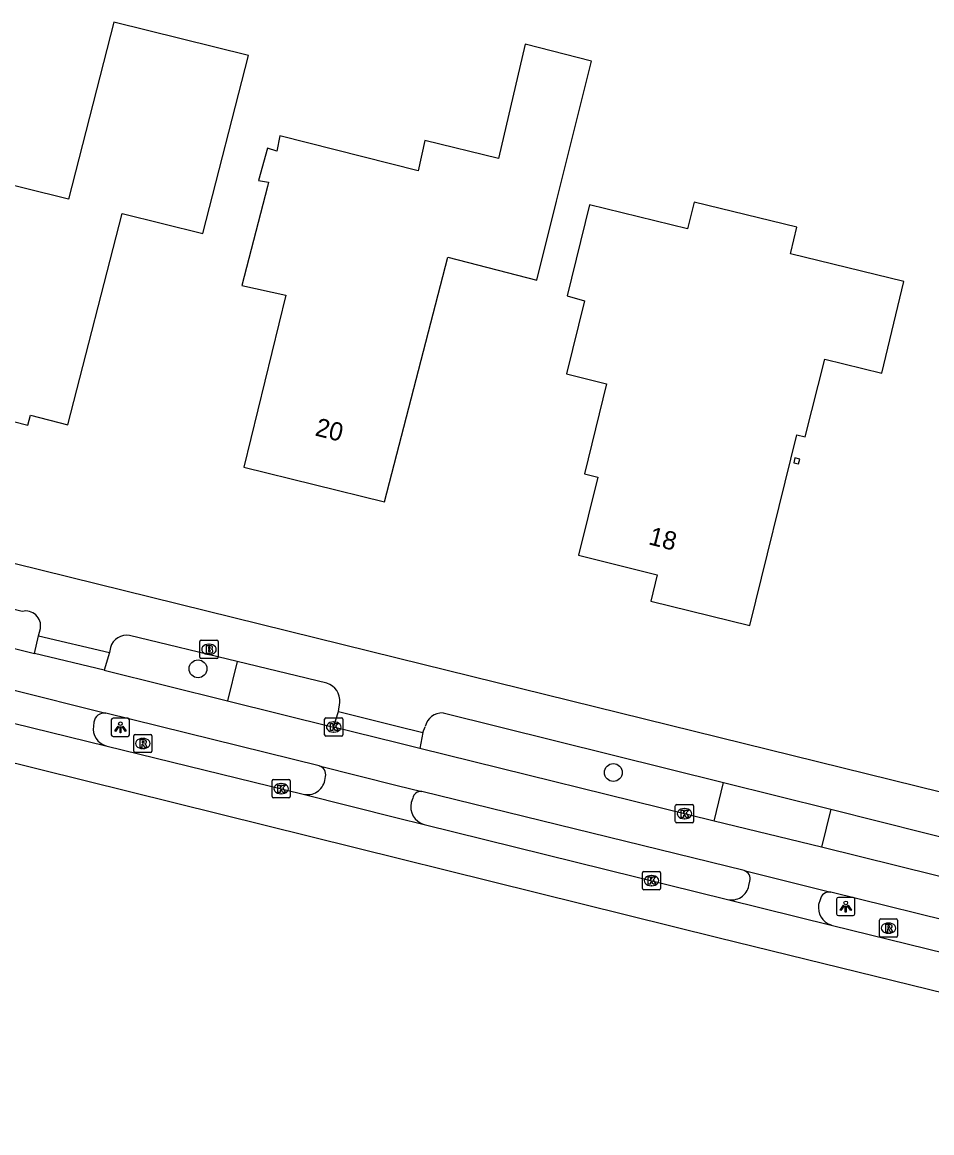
# Model space of a CAD drawing. Extents: x 161354 to 161876, y 382161 to 382804.
# Drawn here: x 161479.4 to 161529.3, y 382164.9 to 382225.8 of the extents above; entities that cross this region are included whole.
import ezdxf

# ---------------------------------------------------------------- set-up
doc = ezdxf.new("R2010")
doc.units = 0
for name, color, linetype in [('IMGEO_Berm_groen', 7, 'Continuous'), ('IMGEO_Boom', 7, 'Continuous'), ('IMGEO_Brandkraan', 7, 'Continuous'), ('IMGEO_Fietspad_gesloten', 7, 'Continuous'), ('IMGEO_Kolk', 7, 'Continuous'), ('IMGEO_Lichtpunt', 7, 'Continuous'), ('IMGEO_Pand', 7, 'Continuous'), ('IMGEO_Pand_nummerreeks', 7, 'Continuous'), ('IMGEO_Parkeervlak_gesloten', 7, 'Continuous'), ('IMGEO_Rijbaan_lokaal_gesloten', 7, 'Continuous'), ('IMGEO_Rioolput', 7, 'Continuous'), ('IMGEO_Voetpad_open', 7, 'Continuous')]:
    doc.layers.add(name, color=color, linetype=linetype)

msp = doc.modelspace()

# ---------------------------------------------------------------- linework, layer by layer
at = {"layer": 'IMGEO_Berm_groen'}
msp.add_lwpolyline([(161491.219, 382190.757), (161490.686, 382188.602)], dxfattribs=at)
at = {"layer": 'IMGEO_Boom'}
for centre in [(161489.073, 382190.355), (161511.843, 382184.67)]:
    msp.add_circle(centre, 0.489, dxfattribs=at)
at = {"layer": 'IMGEO_Brandkraan'}
for p, q in [((161489.175, 382190.993), (161489.175, 382191.845)), ((161489.25, 382191.919), (161490.102, 382191.919)), ((161489.663, 382191.699), (161489.688, 382191.699)), ((161490.176, 382191.845), (161490.176, 382190.993)), ((161490.102, 382190.919), (161489.25, 382190.919)), ((161489.686, 382191.139), (161489.661, 382191.139))]:
    msp.add_line(p, q, dxfattribs=at)
for points in [[(161489.175, 382190.993), (161489.175, 382191.845)], [(161489.25, 382191.919), (161490.102, 382191.919)], [(161489.523, 382191.619), (161489.523, 382191.219), (161489.736, 382191.219)], [(161489.754, 382191.619), (161489.523, 382191.619)], [(161489.702, 382191.538), (161489.648, 382191.538), (161489.648, 382191.462)], [(161490.176, 382191.845), (161490.176, 382190.993)], [(161490.102, 382190.919), (161489.25, 382190.919)], [(161489.648, 382191.462), (161489.701, 382191.462)], [(161489.71, 382191.386), (161489.648, 382191.386), (161489.648, 382191.305)], [(161489.648, 382191.305), (161489.71, 382191.305)]]:
    msp.add_lwpolyline(points, dxfattribs=at)
for centre, radius, start, end in [((161489.252, 382191.843), 0.0765, 91.55205, 178.44795), ((161489.252, 382191.843), 0.0765, 91.55205, 178.44795), ((161489.703, 382191.5), 0.0379, 267.82845, 90.93552), ((161489.758, 382191.474), 0.145, 59.4692, 91.53667), ((161489.783, 382191.521), 0.0922, 285.51372, 58.15012), ((161490.1, 382191.843), 0.0765, 1.55205, 88.44795), ((161490.1, 382191.843), 0.0765, 1.55205, 88.44795), ((161489.252, 382190.995), 0.0765, 181.55205, 268.44795), ((161489.252, 382190.995), 0.0765, 181.55205, 268.44795), ((161489.711, 382191.345), 0.0404, 269.87594, 90.50774), ((161489.742, 382191.47), 0.251, 268.66757, 293.53466), ((161489.788, 382191.329), 0.105, 301.31148, 78.98903), ((161490.1, 382190.995), 0.0765, 271.55205, 358.44795), ((161490.1, 382190.995), 0.0765, 271.55205, 358.44795)]:
    msp.add_arc(centre, radius, start, end, dxfattribs=at)
for centre, major_axis, ratio, start_param, end_param in [((161489.662, 382191.419), (-0.387, 0.002), 0.722429, 4.712389, 7.853982), ((161489.687, 382191.419), (-0.39, 0.002), 0.717154, 1.570796, 4.712389)]:
    msp.add_ellipse(centre, major_axis=major_axis, ratio=ratio, start_param=start_param, end_param=end_param, dxfattribs=at)
at = {"layer": 'IMGEO_Fietspad_gesloten'}
for points in [[(161466.523, 382194.566), (161480.111, 382191.197)], [(161483.93, 382190.272), (161480.111, 382191.197)], [(161483.93, 382190.272), (161490.686, 382188.602)], [(161478.779, 382189.246), (161484.015, 382187.92)], [(161490.686, 382188.602), (161496.51, 382187.162)], [(161495.709, 382185.028), (161484.015, 382187.92)], [(161501.233, 382185.995), (161500, 382186.3), (161496.51, 382187.162)], [(161517.367, 382182.012), (161501.233, 382185.995)], [(161495.709, 382185.028), (161500, 382183.961), (161501.342, 382183.627)], [(161519.01, 382179.306), (161501.342, 382183.627)], [(161523.26, 382180.579), (161517.367, 382182.012)], [(161539.929, 382176.444), (161523.26, 382180.579)], [(161519.01, 382179.306), (161523.769, 382178.11)], [(161539.444, 382174.246), (161523.769, 382178.11)]]:
    msp.add_lwpolyline(points, dxfattribs=at)
at = {"layer": 'IMGEO_Kolk'}
for p, q in [((161496.014, 382186.738), (161496.014, 382187.59)), ((161496.089, 382187.664), (161496.941, 382187.664)), ((161496.502, 382187.444), (161496.527, 382187.444)), ((161497.015, 382187.59), (161497.015, 382186.738)), ((161496.941, 382186.664), (161496.089, 382186.664)), ((161496.525, 382186.884), (161496.5, 382186.884)), ((161493.133, 382183.357), (161493.133, 382184.209)), ((161493.208, 382184.283), (161494.06, 382184.283)), ((161494.134, 382184.209), (161494.134, 382183.357)), ((161493.621, 382184.063), (161493.646, 382184.063)), ((161494.06, 382183.283), (161493.208, 382183.283)), ((161493.644, 382183.503), (161493.619, 382183.503)), ((161515.242, 382181.987), (161515.242, 382182.839)), ((161515.317, 382182.913), (161516.169, 382182.913)), ((161515.73, 382182.693), (161515.755, 382182.693)), ((161516.243, 382182.839), (161516.243, 382181.987)), ((161516.169, 382181.913), (161515.317, 382181.913)), ((161515.753, 382182.133), (161515.728, 382182.133)), ((161513.435, 382178.322), (161513.435, 382179.174)), ((161513.51, 382179.248), (161514.362, 382179.248)), ((161513.923, 382179.028), (161513.948, 382179.028)), ((161514.436, 382179.174), (161514.436, 382178.322)), ((161514.362, 382178.248), (161513.51, 382178.248)), ((161513.946, 382178.468), (161513.921, 382178.468))]:
    msp.add_line(p, q, dxfattribs=at)
for points in [[(161496.014, 382186.738), (161496.014, 382187.59)], [(161496.089, 382187.664), (161496.941, 382187.664)], [(161496.335, 382187.364), (161496.458, 382187.364), (161496.458, 382187.213), (161496.588, 382187.364), (161496.752, 382187.364), (161496.606, 382187.213), (161496.759, 382186.964), (161496.607, 382186.964), (161496.522, 382187.128), (161496.458, 382187.061), (161496.458, 382186.964), (161496.335, 382186.964), (161496.335, 382187.364)], [(161497.015, 382187.59), (161497.015, 382186.738)], [(161496.941, 382186.664), (161496.089, 382186.664)], [(161493.133, 382183.357), (161493.133, 382184.209)], [(161493.208, 382184.283), (161494.06, 382184.283)], [(161494.134, 382184.209), (161494.134, 382183.357)], [(161493.454, 382183.983), (161493.577, 382183.983), (161493.577, 382183.832), (161493.707, 382183.983), (161493.871, 382183.983), (161493.725, 382183.832), (161493.878, 382183.583), (161493.726, 382183.583), (161493.641, 382183.747), (161493.577, 382183.68), (161493.577, 382183.583), (161493.454, 382183.583), (161493.454, 382183.983)], [(161494.06, 382183.283), (161493.208, 382183.283)], [(161515.242, 382181.987), (161515.242, 382182.839)], [(161515.317, 382182.913), (161516.169, 382182.913)], [(161515.563, 382182.613), (161515.686, 382182.613), (161515.686, 382182.462), (161515.816, 382182.613), (161515.98, 382182.613), (161515.834, 382182.462), (161515.987, 382182.213), (161515.835, 382182.213), (161515.75, 382182.377), (161515.686, 382182.31), (161515.686, 382182.213), (161515.563, 382182.213), (161515.563, 382182.613)], [(161516.243, 382182.839), (161516.243, 382181.987)], [(161516.169, 382181.913), (161515.317, 382181.913)], [(161513.435, 382178.322), (161513.435, 382179.174)], [(161513.51, 382179.248), (161514.362, 382179.248)], [(161513.756, 382178.948), (161513.879, 382178.948), (161513.879, 382178.797), (161514.009, 382178.948), (161514.173, 382178.948), (161514.027, 382178.797), (161514.18, 382178.548), (161514.028, 382178.548), (161513.943, 382178.712), (161513.879, 382178.645), (161513.879, 382178.548), (161513.756, 382178.548), (161513.756, 382178.948)], [(161514.436, 382179.174), (161514.436, 382178.322)], [(161514.362, 382178.248), (161513.51, 382178.248)]]:
    msp.add_lwpolyline(points, dxfattribs=at)
for centre, start, end in [((161496.091, 382187.588), 91.55205, 178.44795), ((161496.091, 382187.588), 91.55205, 178.44795), ((161496.939, 382187.588), 1.55205, 88.44795), ((161496.939, 382187.588), 1.55205, 88.44795), ((161496.091, 382186.74), 181.55205, 268.44795), ((161496.091, 382186.74), 181.55205, 268.44795), ((161496.939, 382186.74), 271.55205, 358.44795), ((161496.939, 382186.74), 271.55205, 358.44795), ((161493.21, 382184.207), 91.55205, 178.44795), ((161493.21, 382184.207), 91.55205, 178.44795), ((161494.058, 382184.207), 1.55205, 88.44795), ((161494.058, 382184.207), 1.55205, 88.44795), ((161493.21, 382183.359), 181.55205, 268.44795), ((161493.21, 382183.359), 181.55205, 268.44795), ((161494.058, 382183.359), 271.55205, 358.44795), ((161494.058, 382183.359), 271.55205, 358.44795), ((161515.319, 382182.837), 91.55205, 178.44795), ((161515.319, 382182.837), 91.55205, 178.44795), ((161516.167, 382182.837), 1.55205, 88.44795), ((161516.167, 382182.837), 1.55205, 88.44795), ((161515.319, 382181.989), 181.55205, 268.44795), ((161515.319, 382181.989), 181.55205, 268.44795), ((161516.167, 382181.989), 271.55205, 358.44795), ((161516.167, 382181.989), 271.55205, 358.44795), ((161513.512, 382179.172), 91.55205, 178.44795), ((161513.512, 382179.172), 91.55205, 178.44795), ((161514.36, 382179.172), 1.55205, 88.44795), ((161514.36, 382179.172), 1.55205, 88.44795), ((161513.512, 382178.324), 181.55205, 268.44795), ((161513.512, 382178.324), 181.55205, 268.44795), ((161514.36, 382178.324), 271.55205, 358.44795), ((161514.36, 382178.324), 271.55205, 358.44795)]:
    msp.add_arc(centre, 0.0765, start, end, dxfattribs=at)
for centre, major_axis, ratio, start_param, end_param in [((161496.501, 382187.164), (-0.387, 0.002), 0.722429, 4.712389, 7.853982), ((161496.526, 382187.164), (-0.39, 0.002), 0.717154, 1.570796, 4.712389), ((161493.62, 382183.783), (-0.387, 0.002), 0.722429, 4.712389, 7.853982), ((161493.645, 382183.783), (-0.39, 0.002), 0.717154, 1.570796, 4.712389), ((161515.729, 382182.413), (-0.387, 0.002), 0.722429, 4.712389, 7.853982), ((161515.754, 382182.413), (-0.39, 0.002), 0.717154, 1.570796, 4.712389), ((161513.922, 382178.748), (-0.387, 0.002), 0.722429, 4.712389, 7.853982), ((161513.947, 382178.748), (-0.39, 0.002), 0.717154, 1.570796, 4.712389)]:
    msp.add_ellipse(centre, major_axis=major_axis, ratio=ratio, start_param=start_param, end_param=end_param, dxfattribs=at)
at = {"layer": 'IMGEO_Lichtpunt'}
for p, q in [((161484.321, 382187.549), (161484.321, 382186.742)), ((161484.321, 382187.549), (161484.321, 382186.742)), ((161485.223, 382187.644), (161484.415, 382187.644)), ((161485.223, 382187.644), (161484.415, 382187.644)), ((161485.317, 382186.742), (161485.317, 382187.549)), ((161485.317, 382186.742), (161485.317, 382187.549)), ((161484.415, 382186.648), (161485.223, 382186.648)), ((161484.415, 382186.648), (161485.223, 382186.648)), ((161524.085, 382177.73), (161524.085, 382176.923)), ((161524.085, 382177.73), (161524.085, 382176.923)), ((161524.987, 382177.825), (161524.179, 382177.825)), ((161524.987, 382177.825), (161524.179, 382177.825)), ((161525.081, 382176.923), (161525.081, 382177.73)), ((161525.081, 382176.923), (161525.081, 382177.73)), ((161524.179, 382176.829), (161524.987, 382176.829)), ((161524.179, 382176.829), (161524.987, 382176.829))]:
    msp.add_line(p, q, dxfattribs=at)
for points in [[(161484.695, 382187.213), (161484.734, 382187.185), (161484.546, 382186.923), (161484.508, 382186.95), (161484.695, 382187.213)], [(161484.797, 382187.165), (161484.844, 382187.165), (161484.844, 382186.843), (161484.797, 382186.843), (161484.797, 382187.165)], [(161484.907, 382187.185), (161484.945, 382187.212), (161485.132, 382186.95), (161485.093, 382186.922), (161484.907, 382187.185)], [(161524.459, 382177.394), (161524.498, 382177.366), (161524.31, 382177.104), (161524.272, 382177.131), (161524.459, 382177.394)], [(161524.561, 382177.346), (161524.608, 382177.346), (161524.608, 382177.024), (161524.561, 382177.024), (161524.561, 382177.346)], [(161524.671, 382177.366), (161524.709, 382177.393), (161524.896, 382177.131), (161524.857, 382177.103), (161524.671, 382177.366)]]:
    msp.add_lwpolyline(points, dxfattribs=at)
for centre in [(161484.82, 382187.347), (161524.584, 382177.528)]:
    msp.add_circle(centre, 0.0994, dxfattribs=at)
for centre, start, end in [((161484.415, 382187.549), 90, 180), ((161484.415, 382187.549), 90, 180), ((161485.223, 382187.549), 0, 90), ((161485.223, 382187.549), 0, 90), ((161484.415, 382186.742), 180, 270), ((161484.415, 382186.742), 180, 270), ((161485.223, 382186.742), 270, 0), ((161485.223, 382186.742), 270, 360), ((161524.179, 382177.73), 90, 180), ((161524.179, 382177.73), 90, 180), ((161524.987, 382177.73), 0, 90), ((161524.987, 382177.73), 0, 90), ((161524.179, 382176.923), 180, 270), ((161524.179, 382176.923), 180, 270), ((161524.987, 382176.923), 270, 0), ((161524.987, 382176.923), 270, 360)]:
    msp.add_arc(centre, 0.0946, start, end, dxfattribs=at)
at = {"layer": 'IMGEO_Pand'}
for points in [[(161484.459, 382225.785), (161481.965, 382216.09), (161477.091, 382217.295), (161476.9, 382216.551), (161473.081, 382217.533), (161471.884, 382212.879), (161475.703, 382211.897), (161475.345, 382210.506), (161474.099, 382205.663), (161476.213, 382205.119), (161476.089, 382204.639), (161479.751, 382203.697), (161479.893, 382204.252), (161481.938, 382203.726), (161484.914, 382215.295), (161489.341, 382214.202), (161491.85, 382223.959), (161484.459, 382225.785)], [(161508.729, 382215.981), (161510.648, 382223.645), (161507.016, 382224.582), (161505.542, 382218.319), (161501.504, 382219.306), (161501.15, 382217.643), (161493.555, 382219.55), (161493.402, 382218.712), (161492.879, 382218.892), (161492.391, 382217.106), (161492.938, 382217.024), (161492.876, 382216.785), (161491.483, 382211.351), (161493.883, 382210.831), (161491.579, 382201.405), (161499.302, 382199.501), (161502.772, 382212.918), (161507.646, 382211.657), (161508.729, 382215.981)], [(161523.431, 382207.322), (161526.554, 382206.562), (161527.773, 382211.569), (161521.55, 382213.087), (161521.571, 382213.17), (161521.906, 382214.547), (161516.273, 382215.92), (161515.918, 382214.462), (161510.528, 382215.776), (161509.311, 382210.784), (161510.262, 382210.524), (161509.284, 382206.511), (161511.472, 382205.978), (161510.26, 382201.041), (161510.991, 382200.854), (161509.937, 382196.584), (161514.255, 382195.504), (161513.891, 382194.058), (161519.33, 382192.723), (161521.898, 382203.183), (161522.367, 382203.068), (161523.431, 382207.322)], [(161522.064, 382201.847), (161521.802, 382201.912), (161521.737, 382201.649), (161522, 382201.585), (161522.064, 382201.847)]]:
    msp.add_lwpolyline(points, dxfattribs=at)
at = {"layer": 'IMGEO_Parkeervlak_gesloten'}
for points in [[(161484.029, 382186.14), (161494.84, 382183.482)], [(161501.466, 382181.829), (161518.095, 382177.712)], [(161523.782, 382176.315), (161538.439, 382172.703)]]:
    msp.add_lwpolyline(points, dxfattribs=at)
at = {"layer": 'IMGEO_Rijbaan_lokaal_gesloten'}
msp.add_lwpolyline([(161562.35, 382164.929), (161553.188, 382166.887), (161517.576, 382175.615), (161453.047, 382191.62), (161425.904, 382198.493)], dxfattribs=at)
at = {"layer": 'IMGEO_Rioolput'}
for p, q in [((161485.549, 382185.834), (161485.549, 382186.686)), ((161485.624, 382186.76), (161486.476, 382186.76)), ((161486.55, 382186.686), (161486.55, 382185.834)), ((161486.037, 382186.54), (161486.062, 382186.54)), ((161486.476, 382185.76), (161485.624, 382185.76)), ((161486.06, 382185.98), (161486.035, 382185.98)), ((161526.428, 382175.719), (161526.428, 382176.571)), ((161526.503, 382176.645), (161527.355, 382176.645)), ((161526.916, 382176.425), (161526.941, 382176.425)), ((161527.429, 382176.571), (161527.429, 382175.719)), ((161526.939, 382175.865), (161526.914, 382175.865)), ((161527.355, 382175.645), (161526.503, 382175.645))]:
    msp.add_line(p, q, dxfattribs=at)
for points in [[(161485.549, 382185.834), (161485.549, 382186.686)], [(161485.624, 382186.76), (161486.476, 382186.76)], [(161486.55, 382186.686), (161486.55, 382185.834)], [(161486.138, 382186.458), (161485.886, 382186.46), (161485.886, 382186.06)], [(161485.886, 382186.06), (161486.01, 382186.06), (161486.01, 382186.222), (161486.021, 382186.222)], [(161486.064, 382186.379), (161486.01, 382186.379), (161486.01, 382186.298)], [(161486.01, 382186.298), (161486.062, 382186.298)], [(161486.068, 382186.193), (161486.139, 382186.06), (161486.279, 382186.06), (161486.214, 382186.186)], [(161486.476, 382185.76), (161485.624, 382185.76)], [(161526.428, 382175.719), (161526.428, 382176.571)], [(161526.503, 382176.645), (161527.355, 382176.645)], [(161527.017, 382176.343), (161526.765, 382176.345), (161526.765, 382175.945)], [(161527.429, 382176.571), (161527.429, 382175.719)], [(161526.765, 382175.945), (161526.889, 382175.945), (161526.889, 382176.107), (161526.9, 382176.107)], [(161526.943, 382176.264), (161526.889, 382176.264), (161526.889, 382176.183)], [(161526.889, 382176.183), (161526.941, 382176.183)], [(161526.947, 382176.078), (161527.018, 382175.945), (161527.158, 382175.945), (161527.093, 382176.071)], [(161527.355, 382175.645), (161526.503, 382175.645)]]:
    msp.add_lwpolyline(points, dxfattribs=at)
for centre, radius, start, end in [((161485.626, 382186.684), 0.0765, 91.55205, 178.44795), ((161485.626, 382186.684), 0.0765, 91.55205, 178.44795), ((161486.474, 382186.684), 0.0765, 1.55205, 88.44795), ((161486.474, 382186.684), 0.0765, 1.55205, 88.44795), ((161486.02, 382186.169), 0.0533, 26.02933, 88.69889), ((161486.046, 382186.487), 0.19, 274.7715, 282.96867), ((161486.07, 382186.283), 0.0964, 77.00612, 93.18647), ((161486.084, 382186.34), 0.0378, 276.66336, 79.67722), ((161486.137, 382186.348), 0.109, 350.36119, 89.41601), ((161486.135, 382186.348), 0.112, 277.58423, 350.98172), ((161486.119, 382186.133), 0.108, 29.51342, 73.79051), ((161485.626, 382185.836), 0.0765, 181.55205, 268.44795), ((161485.626, 382185.836), 0.0765, 181.55205, 268.44795), ((161486.474, 382185.836), 0.0765, 271.55205, 358.44795), ((161486.474, 382185.836), 0.0765, 271.55205, 358.44795), ((161526.505, 382176.569), 0.0765, 91.55205, 178.44795), ((161526.505, 382176.569), 0.0765, 91.55205, 178.44795), ((161527.016, 382176.233), 0.109, 350.36119, 89.41601), ((161527.353, 382176.569), 0.0765, 1.55205, 88.44795), ((161527.353, 382176.569), 0.0765, 1.55205, 88.44795), ((161526.505, 382175.721), 0.0765, 181.55205, 268.44795), ((161526.505, 382175.721), 0.0765, 181.55205, 268.44795), ((161526.899, 382176.054), 0.0533, 26.02933, 88.69889), ((161526.925, 382176.372), 0.19, 274.7715, 282.96867), ((161526.949, 382176.168), 0.0964, 77.00612, 93.18647), ((161526.963, 382176.225), 0.0378, 276.66336, 79.67722), ((161527.014, 382176.233), 0.112, 277.58423, 350.98172), ((161526.998, 382176.018), 0.108, 29.51342, 73.79051), ((161527.353, 382175.721), 0.0765, 271.55205, 358.44795), ((161527.353, 382175.721), 0.0765, 271.55205, 358.44795)]:
    msp.add_arc(centre, radius, start, end, dxfattribs=at)
for centre, major_axis, ratio, start_param, end_param in [((161486.036, 382186.26), (-0.387, 0.002), 0.722429, 4.712389, 7.853982), ((161486.061, 382186.26), (-0.39, 0.002), 0.717154, 1.570796, 4.712389), ((161526.915, 382176.145), (-0.387, 0.002), 0.722429, 4.712389, 7.853982), ((161526.94, 382176.145), (-0.39, 0.002), 0.717154, 1.570796, 4.712389)]:
    msp.add_ellipse(centre, major_axis=major_axis, ratio=ratio, start_param=start_param, end_param=end_param, dxfattribs=at)
at = {"layer": 'IMGEO_Voetpad_open'}
for points in [[(161540.678, 382180.901), (161500, 382190.938), (161464.013, 382199.817), (161420.378, 382210.687)], [(161479.435, 382193.502), (161467.037, 382196.636)], [(161480.111, 382191.197), (161480.334, 382192.164)], [(161480.334, 382192.164), (161480.435, 382192.564)], [(161480.334, 382192.164), (161484.214, 382191.252)], [(161491.219, 382190.757), (161485.326, 382192.186)], [(161484.274, 382191.525), (161484.214, 382191.252)], [(161484.214, 382191.252), (161483.93, 382190.272)], [(161496.136, 382189.565), (161491.219, 382190.757)], [(161496.773, 382188.02), (161496.841, 382188.503)], [(161496.51, 382187.162), (161496.773, 382188.02)], [(161496.773, 382188.02), (161500, 382187.213), (161501.403, 382186.862)], [(161502.505, 382187.939), (161517.888, 382184.124)], [(161477.906, 382187.637), (161484.029, 382186.14)], [(161483.367, 382187.433), (161483.342, 382187.208)], [(161501.403, 382186.862), (161501.233, 382185.995)], [(161501.403, 382186.862), (161501.525, 382187.183)], [(161496.027, 382184.236), (161496.071, 382184.453)], [(161517.367, 382182.012), (161517.888, 382184.124)], [(161517.888, 382184.124), (161523.76, 382182.658)], [(161494.84, 382183.482), (161500, 382182.195), (161501.466, 382181.829)], [(161500.854, 382183.262), (161500.76, 382183.024)], [(161523.76, 382182.658), (161523.26, 382180.579)], [(161523.76, 382182.658), (161539.452, 382178.724)], [(161519.272, 382178.474), (161519.326, 382178.721)], [(161518.095, 382177.712), (161523.782, 382176.315)], [(161523.184, 382177.703), (161523.094, 382177.434)]]:
    msp.add_lwpolyline(points, dxfattribs=at)
for centre, radius, start, end in [((161479.626, 382192.704), 0.821, 350.21173, 103.453), ((161485.169, 382191.269), 0.931, 80.27261, 164.0119), ((161495.84, 382188.603), 1.006, 354.27975, 72.87599), ((161483.92, 382187.372), 0.556, 80.12388, 173.72901), ((161502.481, 382186.958), 0.982, 88.57047, 166.72477), ((161484.28, 382187.056), 0.95, 170.80329, 254.69969), ((161495.588, 382184.551), 0.492, 348.57478, 75.8114), ((161495.063, 382184.443), 0.986, 256.95349, 347.89515), ((161501.285, 382183.194), 0.436, 82.50601, 171.08335), ((161501.73, 382182.791), 0.998, 166.5105, 254.63826), ((161518.853, 382178.843), 0.489, 345.53871, 71.21454), ((161518.318, 382178.657), 0.971, 256.72206, 349.11668), ((161523.677, 382177.619), 0.5, 79.33641, 170.31831), ((161524.095, 382177.279), 1.013, 171.1712, 251.99808)]:
    msp.add_arc(centre, radius, start, end, dxfattribs=at)

# ---------------------------------------------------------------- texts
at = {"layer": 'IMGEO_Pand_nummerreeks'}
for s, rotation, p in [('20', 346.2662, (161495.443, 382203.146)), ('18', 345.762, (161513.725, 382197.185))]:
    msp.add_text(s, height=1, rotation=rotation, dxfattribs=at).set_placement(p)

doc.saveas('drawing.dxf')
